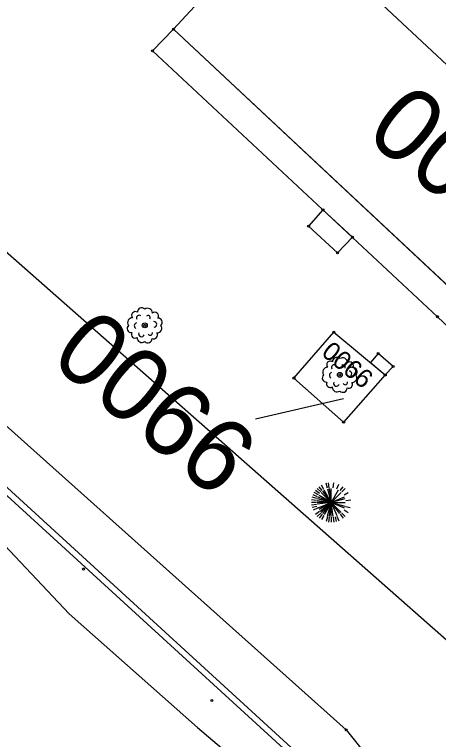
# Model space of a CAD drawing. Extents: x 344013 to 344423, y 298505 to 298795.
# Drawn here: x 344132.25 to 344153.42, y 298669.85 to 298706.06 of the extents above; entities that cross this region are included whole.
import ezdxf

# ---------------------------------------------------------------- set-up
doc = ezdxf.new("R2010")
doc.units = 0
for name, color, linetype in [('Default', 7, 'Continuous'), ('DH_CADRE -CARTOUCHE', 7, 'Continuous'), ('GO MUR EXTERIEUR', 7, 'Continuous'), ('PS_BOLT', 7, 'Continuous'), ('PS_CONST', 7, 'Continuous'), ('TOPO_POINT', 7, 'Continuous'), ('VOIRIE_BORDURE', 7, 'Continuous'), ('VOIRIE_ESPACE VERT', 7, 'Continuous')]:
    doc.layers.add(name, color=color, linetype=linetype)

# ---------------------------------------------------------------- blocks, each defined once
blk = doc.blocks.new('POINT_DISPLAY')
at = {"layer": 'Default'}
blk.add_circle((0, 0), 0.05, dxfattribs=at)
blk = doc.blocks.new('ARB1')
at = {"layer": 'Default'}
blk.add_circle((0, 0), 0.122, dxfattribs=at)
for centre, radius, start, end in [((-0.153, 0.664), 0.211, 43.6925, 183.5969), ((0.139, 0.613), 0.241, 358.4583, 125.1928), ((-0.613, 0.139), 0.241, 88.4583, 215.1928), ((-0.471, 0.503), 0.183, 53.9554, 222.2066), ((-0.276, 0.37), 0.134, 52.4396, 209.5496), ((0.164, 0.38), 0.112, 330.5895, 133.7127), ((0.501, 0.468), 0.183, 325.1444, 131.0175), ((0.664, 0.153), 0.211, 313.6925, 93.5969), ((-0.373, -0.024), 0.149, 103.7092, 242.3465), ((0.458, 0.052), 0.137, 276.6214, 88.967), ((0.613, -0.139), 0.241, 268.4583, 35.1928), ((-0.664, -0.153), 0.211, 133.6925, 273.5969), ((0.271, -0.38), 0.112, 210.5895, 13.7127), ((-0.478, -0.443), 0.19, 155.2243, 300.9377), ((-0.139, -0.613), 0.241, 178.4583, 305.1928), ((-0.163, -0.42), 0.148, 159.5371, 338.1663), ((0.153, -0.664), 0.211, 223.6925, 3.5969), ((0.448, -0.483), 0.188, 243.1323, 33.0297)]:
    blk.add_arc(centre, radius, start, end, dxfattribs=at)
blk = doc.blocks.new('ARB2')
at = {"layer": 'Default'}
for p, q in [((-0.438, 0.589), (-0.588, 0.786)), ((-0.356, 0.642), (-0.481, 0.858)), ((-0.181, 0.716), (-0.244, 0.956)), ((-0.088, 0.736), (-0.119, 0.983)), ((0.106, 0.736), (0.144, 0.983)), ((0.287, 0.684), (0.388, 0.914)), ((0.456, 0.589), (0.612, 0.786)), ((-0.675, 0.286), (-0.9, 0.381)), ((-0.631, 0.373), (-0.844, 0.497)), ((-0.575, 0.453), (-0.775, 0.605)), ((-0.513, 0.525), (-0.688, 0.702)), ((0.531, 0.525), (0.706, 0.702)), ((0.65, 0.373), (0.862, 0.497)), ((-0.731, 0), (-0.981, 0)), ((-0.725, 0.1), (-0.969, 0.133)), ((-0.706, 0.195), (-0.944, 0.259)), ((0.744, 0.1), (0.987, 0.133)), ((-0.725, -0.1), (-0.969, -0.133)), ((-0.706, -0.195), (-0.944, -0.259)), ((-0.675, -0.287), (-0.9, -0.383)), ((0.725, -0.195), (0.963, -0.259)), ((-0.575, -0.455), (-0.775, -0.605)), ((-0.513, -0.527), (-0.688, -0.702)), ((-0.438, -0.591), (-0.588, -0.787)), ((-0.356, -0.644), (-0.481, -0.859)), ((-0.181, -0.717), (-0.244, -0.956)), ((0.2, -0.717), (0.263, -0.956)), ((0.287, -0.686), (0.388, -0.916)), ((0.456, -0.591), (0.612, -0.787)), ((0.531, -0.527), (0.706, -0.702)), ((0.65, -0.373), (0.862, -0.498)), ((-0.088, -0.737), (-0.119, -0.983)), ((0.013, -0.741), (0.013, -0.989)), ((0.106, -0.737), (0.144, -0.983))]:
    blk.add_line(p, q, dxfattribs=at)
for points in [[(-0.688, 0.091), (0.013, 0), (-0.338, 0.608)], [(-0.487, 0.495), (0.013, 0), (-0.669, 0.181)], [(-0.419, 0.556), (0.013, 0), (-0.638, 0.269)], [(-0.169, 0.677), (0.013, 0), (-0.6, 0.35)], [(0.013, 0.008), (0.013, 0), (-0.081, 0.695)], [(0.362, 0.608), (0.013, 0), (0.013, 0.702)], [(0.656, 0.269), (0.013, 0), (0.506, 0.495)], [(-0.487, -0.497), (0.013, 0), (-0.694, 0)], [(-0.638, -0.269), (0.013, 0), (-0.688, -0.092)], [(-0.169, -0.678), (0.013, 0), (-0.6, -0.352)], [(-0.544, -0.428), (0.013, 0), (-0.338, -0.608)], [(-0.081, -0.695), (0.013, 0), (-0.419, -0.558)], [(0.013, -0.702), (0.013, 0), (0, 0)], [(0.688, 0.181), (0.013, 0), (0.713, 0)], [(0.438, -0.558), (0.013, 0), (0.656, -0.269)], [(0.506, -0.497), (0.013, 0), (0.688, -0.181)], [(0.1, -0.695), (0.013, 0), (0.281, -0.648)], [(0.019, 0), (0.013, 0), (0.013, -0.009)]]:
    blk.add_lwpolyline(points, dxfattribs=at)

msp = doc.modelspace()

# ---------------------------------------------------------------- linework, layer by layer
at = {"layer": 'DH_CADRE -CARTOUCHE'}
msp.add_lwpolyline([(344163.929, 298683.13), (344165.092, 298684.375), (344155.123, 298693.692), (344153.96, 298692.447), (344140.184, 298705.334), (344145.624, 298711.233), (344171.024, 298687.508), (344165.544, 298681.621)], close=True, dxfattribs=at)
at = {"layer": 'GO MUR EXTERIEUR'}
msp.add_lwpolyline([(344145.624, 298711.233), (344171.024, 298687.508), (344165.544, 298681.621), (344140.184, 298705.334)], close=True, dxfattribs=at)
at = {"layer": 'PS_BOLT'}
msp.add_lwpolyline([(344165.544, 298681.621), (344165.531, 298681.558), (344168.3, 298678.926), (344167.289, 298677.848), (344153.365, 298690.972), (344139.141, 298704.253), (344140.184, 298705.334)], dxfattribs=at)
for points in [[(344146.936, 298695.487), (344148.382, 298694.163), (344149.131, 298694.945), (344147.653, 298696.304)], [(344148.685, 298685.7), (344146.205, 298687.907), (344148.199, 298690.2), (344150.764, 298688.06)], [(344150.764, 298688.06), (344151.158, 298688.481), (344150.409, 298689.131), (344150.019, 298688.681)]]:
    msp.add_lwpolyline(points, close=True, dxfattribs=at)
at = {"layer": 'PS_CONST'}
msp.add_line((344144.279, 298685.866), (344148.684, 298686.887), dxfattribs=at)
at = {"layer": 'VOIRIE_BORDURE'}
for points in [[(344128.542, 298697.099), (344156.76, 298672.229), (344158.923, 298671.699), (344160.816, 298671.605), (344163.478, 298672.279), (344165.611, 298673.484), (344167.1, 298674.65), (344168.229, 298675.97), (344185.426, 298693.989), (344196.039, 298705.71), (344211.949, 298722.43)], [(344124.372, 298692.186), (344148.812, 298670.333), (344149.478, 298669.504), (344150.054, 298668.628), (344150.475, 298667.688), (344150.721, 298667.085), (344151.432, 298665.306), (344151.673, 298664.395), (344151.676, 298663.909), (344143.5, 298656.169), (344142.683, 298655.44), (344135.602, 298647.623), (344124.992, 298635.682)]]:
    msp.add_lwpolyline(points, dxfattribs=at)
at = {"layer": 'VOIRIE_ESPACE VERT'}
msp.add_lwpolyline([(344129.915, 298683.811), (344149.954, 298665.484), (344120.649, 298634.816), (344119.758, 298634.843), (344094.693, 298657.614), (344119.626, 298684.533), (344119.467, 298684.803), (344094.267, 298657.595), (344119.638, 298634.546), (344120.774, 298634.512), (344150.383, 298665.499), (344130.117, 298684.033)], close=True, dxfattribs=at)
msp.add_lwpolyline([(344129.834, 298681.573), (344134.972, 298676.138), (344141.382, 298670.447), (344145.984, 298666.555), (344146.809, 298665.696), (344145.776, 298664.399), (344143.49, 298661.745), (344140.544, 298658.509), (344138.612, 298656.16), (344137.895, 298655.241), (344137.314, 298655.683), (344136.818, 298655.628), (344136.259, 298655.071), (344135.904, 298654.607), (344135.762, 298654.056), (344136.012, 298653.679), (344136.225, 298653.183), (344132.496, 298649.404), (344131.323, 298648.36)], dxfattribs=at)

# ---------------------------------------------------------------- block references
at = {"layer": 'TOPO_POINT'}
for p in [(344140.184, 298705.334), (344139.141, 298704.253), (344147.653, 298696.304), (344146.936, 298695.487), (344149.131, 298694.945), (344148.382, 298694.163), (344153.365, 298690.972), (344138.754, 298690.538), (344148.199, 298690.2), (344150.409, 298689.131), (344151.158, 298688.481), (344146.205, 298687.907), (344148.493, 298688.067), (344150.764, 298688.06), (344148.685, 298685.7), (344148.055, 298681.693), (344135.699, 298678.368), (344142.106, 298671.801), (344148.812, 298670.333)]:
    msp.add_blockref('POINT_DISPLAY', p, dxfattribs=at)
at = {"layer": 'VOIRIE_ESPACE VERT'}
for name, p in [('ARB1', (344138.754, 298690.538)), ('ARB1', (344148.493, 298688.067)), ('ARB2', (344148.055, 298681.693))]:
    msp.add_blockref(name, p, dxfattribs=at)

# ---------------------------------------------------------------- texts
at = {"layer": 'PS_CONST'}
for s, height, p in [('0025', 3.662, (344149.662, 298699.997)), ('0066', 3.662, (344133.922, 298688.769)), ('0066', 0.9308, (344147.522, 298689.094))]:
    msp.add_text(s, height=height, rotation=320.3665, dxfattribs=at).set_placement(p)

doc.saveas('drawing.dxf')
